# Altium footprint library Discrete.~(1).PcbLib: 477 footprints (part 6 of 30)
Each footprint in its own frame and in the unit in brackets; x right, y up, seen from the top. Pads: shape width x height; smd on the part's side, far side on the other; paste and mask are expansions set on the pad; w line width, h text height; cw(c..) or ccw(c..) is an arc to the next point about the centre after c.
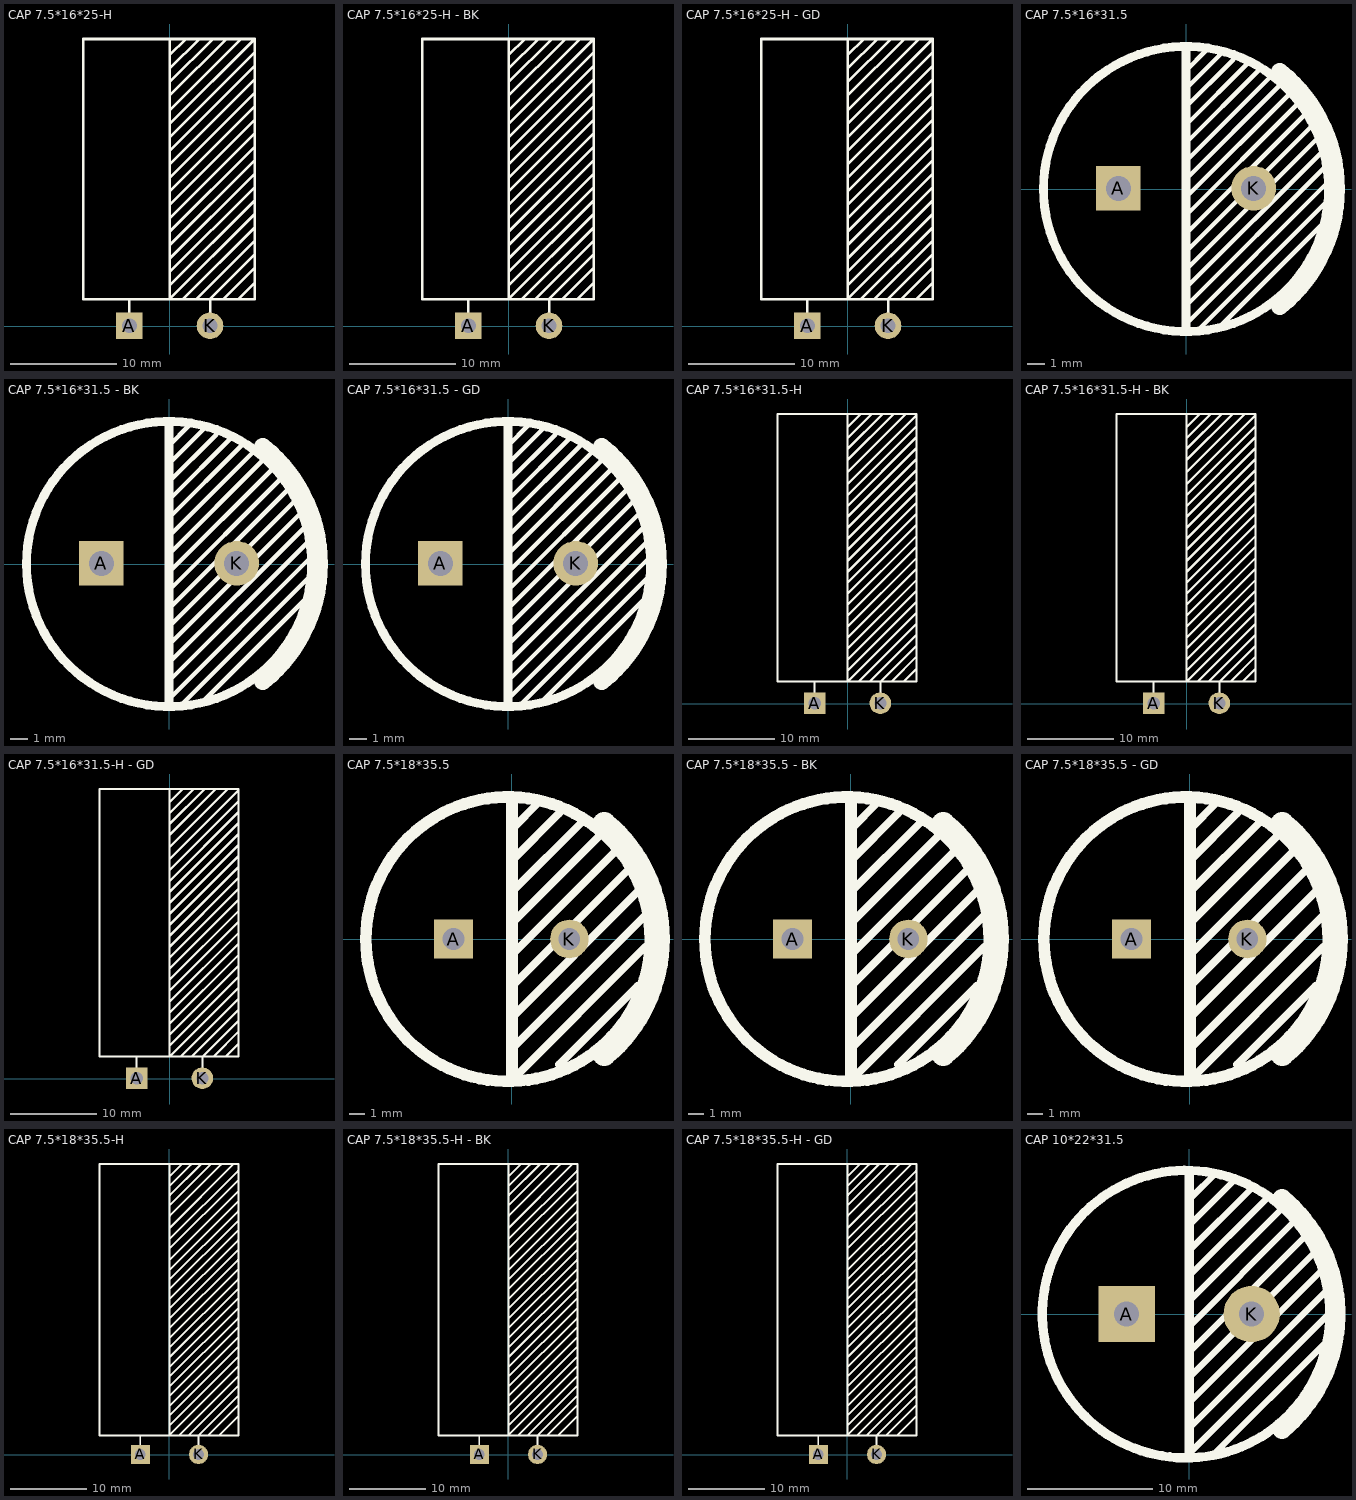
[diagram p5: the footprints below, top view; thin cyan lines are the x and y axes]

## CAP 7.5*16*25-H [mm] "脚距7.5mm直径16mm高度25mm"
pads (2):
  rect 2.5x2.5 hole 1.4: A(-3.8,0.038)
  round 2.5 hole 1.4: K(3.8,0.038)
Top Overlay:
  lines w0.254: -3.81,1.27 -3.81,2.54 ; 0,3.81 8.001,11.811 ; 0,5.08 8.001,13.081 ; 0,6.35 8.001,14.351 ; 0,7.62 7.938,15.557 ; 0,8.89 8.001,16.891 ; 0,10.16 7.938,18.098 ; 0,11.43 8.001,19.431 ; 0,12.7 7.938,20.637 ; 0,13.97 7.938,21.907 ; 0,15.24 7.938,23.177 ; 0,16.51 7.938,24.447 ; 0,17.78 7.938,25.717 ; 0,19.05 7.929,26.979 ; 0,20.32 6.731,27.051 ; 0,21.717 5.334,27.051 ; 0,22.987 4.064,27.051 ; 0,24.257 2.794,27.051 ; 0,25.527 1.524,27.051 ; 0,27.051 0,2.54 8.001,10.541 ; 1.27,2.54 8.001,9.271 ; 2.54,2.54 8.001,8.001 ; 3.81,1.27 3.81,2.54 8.001,6.731 ; 5.08,2.54 8.001,5.461 ; 6.477,2.54 8.001,4.064 ; -8.128,2.54 8.001,2.54 8.001,27.051 -8.128,27.051 -8.128,2.54
3D body "CAP 7.5X16X25-H.STEP": height 16.03, standoff -3.47, extent -8.05,-0.462 7.96,26.948

## CAP 7.5*16*25-H - BK [mm] "脚距7.5mm直径16mm高度25mm"
pads (2):
  rect 2.5x2.5 hole 1.4: A(-3.8,0.038)
  round 2.5 hole 1.4: K(3.8,0.038)
Top Overlay:
  lines w0.254: -3.81,1.27 -3.81,2.54 ; 0,3.81 8.001,11.811 ; 0,5.08 8.001,13.081 ; 0,6.35 8.001,14.351 ; 0,7.62 7.938,15.557 ; 0,8.89 8.001,16.891 ; 0,10.16 7.938,18.098 ; 0,11.43 8.001,19.431 ; 0,12.7 7.938,20.637 ; 0,13.97 7.938,21.907 ; 0,15.24 7.938,23.177 ; 0,16.51 7.938,24.447 ; 0,17.78 7.938,25.717 ; 0,19.05 7.929,26.979 ; 0,20.32 6.731,27.051 ; 0,21.717 5.334,27.051 ; 0,22.987 4.064,27.051 ; 0,24.257 2.794,27.051 ; 0,25.527 1.524,27.051 ; 0,27.051 0,2.54 8.001,10.541 ; 1.27,2.54 8.001,9.271 ; 2.54,2.54 8.001,8.001 ; 3.81,1.27 3.81,2.54 8.001,6.731 ; 5.08,2.54 8.001,5.461 ; 6.477,2.54 8.001,4.064 ; -8.128,2.54 -8.128,27.051 8.001,27.051 8.001,2.54 -8.128,2.54
3D body "CAP 7.5X16X25-H.STEP": height 16.03, standoff -3.48, extent -8.05,-0.462 7.96,26.948

## CAP 7.5*16*25-H - GD [mm] "脚距7.5mm直径16mm高度25mm"
pads (2):
  rect 2.5x2.5 hole 1.4: A(-3.8,0.038)
  round 2.5 hole 1.4: K(3.8,0.038)
Top Overlay:
  lines w0.254: -3.81,1.27 -3.81,2.54 ; 0,3.81 8.001,11.811 ; 0,5.08 8.001,13.081 ; 0,6.35 8.001,14.351 ; 0,7.62 7.938,15.557 ; 0,8.89 8.001,16.891 ; 0,10.16 7.938,18.098 ; 0,11.43 8.001,19.431 ; 0,12.7 7.938,20.637 ; 0,13.97 7.938,21.907 ; 0,15.24 7.938,23.177 ; 0,16.51 7.938,24.447 ; 0,17.78 7.938,25.717 ; 0,19.05 7.929,26.979 ; 0,20.32 6.731,27.051 ; 0,21.717 5.334,27.051 ; 0,22.987 4.064,27.051 ; 0,24.257 2.794,27.051 ; 0,25.527 1.524,27.051 ; 0,27.051 0,2.54 8.001,10.541 ; 1.27,2.54 8.001,9.271 ; 2.54,2.54 8.001,8.001 ; 3.81,1.27 3.81,2.54 8.001,6.731 ; 5.08,2.54 8.001,5.461 ; 6.477,2.54 8.001,4.064 ; -8.128,2.54 -8.128,27.051 8.001,27.051 8.001,2.54 -8.128,2.54
3D body "CAP 7.5X16X25-H.STEP": height 16.03, standoff -3.48, extent -8.05,-0.462 7.96,26.948

## CAP 7.5*16*31.5 [mm] "脚距7.5mm直径16mm高度31.5mm"
pads (2):
  rect 2.5x2.5 hole 1.4: A(-3.8,0.038)
  round 2.5 hole 1.4: K(3.8,0.038)
Top Overlay:
  circle w0.5: c0,0 r8
  lines w0.254: 0,-7.582 8.001,0.419 ; 0,-6.566 7.874,1.308 ; 0,-5.55 7.62,2.07 ; 0,-4.534 7.366,2.832 ; 0,-3.518 6.972,3.454 ; 0,-2.502 6.604,4.102 ; 0,-1.486 6.223,4.737 ; 0,-0.47 5.905,5.436 ; 0,0.546 5.296,5.842 ; 0,1.562 4.826,6.388 ; 0,2.578 4.064,6.642 ; 0,3.594 3.556,7.15 ; 0,4.61 2.54,7.15 2.769,7.379 ; 0,5.626 2.032,7.658 ; 0,6.642 1.143,7.785 ; 0.66,-7.938 7.938,-0.66 ; 2.032,-7.582 6.604,-3.01 7.81,-1.803
  lines w0.5: 0,-7.963 0,7.963
  lines w1: 5.259,-6.574 ccw(c0,0) 5.259,6.574
3D body "CAP 7.5X16X31.STEP": height 31.53, standoff -3.38, extent -8,-7.998 8.01,7.998

## CAP 7.5*16*31.5 - BK [mm] "脚距7.5mm直径16mm高度31.5mm"
pads (2):
  rect 2.5x2.5 hole 1.4: A(-3.8,0.038)
  round 2.5 hole 1.4: K(3.8,0.038)
Top Overlay:
  circle w0.5: c0,0 r8
  lines w0.254: 0,-7.582 8.001,0.419 ; 0,-6.566 7.874,1.308 ; 0,-5.55 7.62,2.07 ; 0,-4.534 7.366,2.832 ; 0,-3.518 6.972,3.454 ; 0,-2.502 6.604,4.102 ; 0,-1.486 6.223,4.737 ; 0,-0.47 5.905,5.436 ; 0,0.546 5.296,5.842 ; 0,1.562 4.826,6.388 ; 0,2.578 4.064,6.642 ; 0,3.594 3.556,7.15 ; 0,4.61 2.54,7.15 2.769,7.379 ; 0,5.626 2.032,7.658 ; 0,6.642 1.143,7.785 ; 0.66,-7.938 7.938,-0.66 ; 2.032,-7.582 6.604,-3.01 7.81,-1.803
  lines w0.5: 0,-7.963 0,7.963
  lines w1: 5.259,-6.574 ccw(c0,0) 5.259,6.574
3D body "CAP 7.5X16X31.5.STEP": height 31.54, standoff -3.37, extent -8,-7.998 8.01,7.998

## CAP 7.5*16*31.5 - GD [mm] "脚距7.5mm直径16mm高度31.5mm"
pads (2):
  rect 2.5x2.5 hole 1.4: A(-3.8,0.038)
  round 2.5 hole 1.4: K(3.8,0.038)
Top Overlay:
  circle w0.5: c0,0 r8
  lines w0.254: 0,-7.582 8.001,0.419 ; 0,-6.566 7.874,1.308 ; 0,-5.55 7.62,2.07 ; 0,-4.534 7.366,2.832 ; 0,-3.518 6.972,3.454 ; 0,-2.502 6.604,4.102 ; 0,-1.486 6.223,4.737 ; 0,-0.47 5.905,5.436 ; 0,0.546 5.296,5.842 ; 0,1.562 4.826,6.388 ; 0,2.578 4.064,6.642 ; 0,3.594 3.556,7.15 ; 0,4.61 2.54,7.15 2.769,7.379 ; 0,5.626 2.032,7.658 ; 0,6.642 1.143,7.785 ; 0.66,-7.938 7.938,-0.66 ; 2.032,-7.582 6.604,-3.01 7.81,-1.803
  lines w0.5: 0,-7.963 0,7.963
  lines w1: 5.259,-6.574 ccw(c0,0) 5.259,6.574
3D body "CAP 7.5X16X31.5.STEP": height 31.54, standoff -3.37, extent -8,-7.998 8.01,7.998

## CAP 7.5*16*31.5-H [mm] "脚距7.5mm直径16mm高度31.5mm"
pads (2):
  rect 2.5x2.5 hole 1.4: A(-3.8,0.038)
  round 2.5 hole 1.4: K(3.8,0.038)
Top Overlay:
  lines w0.254: -3.81,1.27 -3.81,2.54 ; 0,3.81 8.001,11.811 ; 0,5.08 8.001,13.081 ; 0,6.35 8.001,14.351 ; 0,7.62 7.938,15.557 ; 0,8.89 8.001,16.891 ; 0,10.16 7.938,18.098 ; 0,11.43 8.001,19.431 ; 0,12.7 7.938,20.637 ; 0,13.97 7.938,21.907 ; 0,15.24 7.938,23.177 ; 0,16.51 7.938,24.447 ; 0,17.78 7.938,25.717 ; 0,19.05 7.929,26.979 ; 0,20.32 7.938,28.258 ; 0,21.59 7.938,29.527 ; 0,22.86 7.938,30.797 ; 0,24.13 7.938,32.067 ; 0,25.4 7.929,33.329 ; 0,26.797 6.731,33.528 ; 0,28.194 5.334,33.528 ; 0,29.464 4.064,33.528 ; 0,30.734 2.794,33.528 ; 0,32.004 1.524,33.528 ; 0,33.528 0,2.54 8.001,10.541 ; 1.27,2.54 8.001,9.271 ; 2.54,2.54 8.001,8.001 ; 3.81,1.27 3.81,2.54 8.001,6.731 ; 5.08,2.54 8.001,5.461 ; 6.477,2.54 8.001,4.064 ; -8.128,2.54 -8.128,33.528 8.001,33.528 8.001,2.54 -8.128,2.54
3D body "CAP 7.5X16X31.5-H.STEP": height 16.03, standoff -3.47, extent -8.05,-0.462 7.96,33.448

## CAP 7.5*16*31.5-H - BK [mm] "脚距7.5mm直径16mm高度31.5mm"
pads (2):
  rect 2.5x2.5 hole 1.4: A(-3.8,0.038)
  round 2.5 hole 1.4: K(3.8,0.038)
Top Overlay:
  lines w0.254: -3.81,1.27 -3.81,2.54 ; 0,3.81 8.001,11.811 ; 0,5.08 8.001,13.081 ; 0,6.35 8.001,14.351 ; 0,7.62 7.938,15.557 ; 0,8.89 8.001,16.891 ; 0,10.16 7.938,18.098 ; 0,11.43 8.001,19.431 ; 0,12.7 7.938,20.637 ; 0,13.97 7.938,21.907 ; 0,15.24 7.938,23.177 ; 0,16.51 7.938,24.447 ; 0,17.78 7.938,25.717 ; 0,19.05 7.929,26.979 ; 0,20.32 7.938,28.258 ; 0,21.59 7.938,29.527 ; 0,22.86 7.938,30.797 ; 0,24.13 7.938,32.067 ; 0,25.4 7.929,33.329 ; 0,26.797 6.731,33.528 ; 0,28.194 5.334,33.528 ; 0,29.464 4.064,33.528 ; 0,30.734 2.794,33.528 ; 0,32.004 1.524,33.528 ; 0,33.528 0,2.54 8.001,10.541 ; 1.27,2.54 8.001,9.271 ; 2.54,2.54 8.001,8.001 ; 3.81,1.27 3.81,2.54 8.001,6.731 ; 5.08,2.54 8.001,5.461 ; 6.477,2.54 8.001,4.064 ; -8.128,2.54 -8.128,33.528 8.001,33.528 8.001,2.54 -8.128,2.54
3D body "CAP 7.5X16X31.5-H.STEP": height 16.03, standoff -3.48, extent -8.05,-0.462 7.96,33.448

## CAP 7.5*16*31.5-H - GD [mm] "脚距7.5mm直径16mm高度31.5mm"
pads (2):
  rect 2.5x2.5 hole 1.4: A(-3.8,0.038)
  round 2.5 hole 1.4: K(3.8,0.038)
Top Overlay:
  lines w0.254: -3.81,1.27 -3.81,2.54 ; 0,3.81 8.001,11.811 ; 0,5.08 8.001,13.081 ; 0,6.35 8.001,14.351 ; 0,7.62 7.938,15.557 ; 0,8.89 8.001,16.891 ; 0,10.16 7.938,18.098 ; 0,11.43 8.001,19.431 ; 0,12.7 7.938,20.637 ; 0,13.97 7.938,21.907 ; 0,15.24 7.938,23.177 ; 0,16.51 7.938,24.447 ; 0,17.78 7.938,25.717 ; 0,19.05 7.929,26.979 ; 0,20.32 7.938,28.258 ; 0,21.59 7.938,29.527 ; 0,22.86 7.938,30.797 ; 0,24.13 7.938,32.067 ; 0,25.4 7.929,33.329 ; 0,26.797 6.731,33.528 ; 0,28.194 5.334,33.528 ; 0,29.464 4.064,33.528 ; 0,30.734 2.794,33.528 ; 0,32.004 1.524,33.528 ; 0,33.528 0,2.54 8.001,10.541 ; 1.27,2.54 8.001,9.271 ; 2.54,2.54 8.001,8.001 ; 3.81,1.27 3.81,2.54 8.001,6.731 ; 5.08,2.54 8.001,5.461 ; 6.477,2.54 8.001,4.064 ; -8.128,2.54 -8.128,33.528 8.001,33.528 8.001,2.54 -8.128,2.54
3D body "CAP 7.5X16X31.5-H.STEP": height 16.03, standoff -3.48, extent -8.05,-0.462 7.96,33.448

## CAP 7.5*18*35.5 [mm] "脚距7.5mm直径18mm高度35.5mm"
pads (2):
  rect 2.5x2.5 hole 1.4: A(-3.78,0)
  round 2.5 hole 1.4: K(3.72,0)
Top Overlay:
  circle w0.754: c-0.248,-0.013 r9.2
  lines w0.504: 0,-9.144 8.636,-0.508 ; 0,-7.112 8.636,1.524 ; 0,-5.08 8.128,3.048 ; 0,-3.048 7.62,4.572 ; 0,-1.016 6.731,5.715 ; 0,1.016 5.715,6.731 ; 0,3.048 4.572,7.62 ; 0,5.08 3.048,8.128 ; 0,7.112 1.778,8.89 ; 3.048,-8.128 8.128,-3.048
  lines w0.754: 0,-8.8 0,8.8
  lines w1.524: 5.959,-7.456 ccw(c-0.254,0) 5.959,7.456
3D body "CAP 7.5X18X35.5.STEP": height 35.54, standoff -3.37, extent -9,-8.997 9.01,8.997

## CAP 7.5*18*35.5 - BK [mm] "脚距7.5mm直径18mm高度35.5mm"
pads (2):
  rect 2.5x2.5 hole 1.4: A(-3.78,0)
  round 2.5 hole 1.4: K(3.72,0)
Top Overlay:
  circle w0.754: c-0.248,-0.013 r9.2
  lines w0.504: 0,-9.144 8.636,-0.508 ; 0,-7.112 8.636,1.524 ; 0,-5.08 8.128,3.048 ; 0,-3.048 7.62,4.572 ; 0,-1.016 6.731,5.715 ; 0,1.016 5.715,6.731 ; 0,3.048 4.572,7.62 ; 0,5.08 3.048,8.128 ; 0,7.112 1.778,8.89 ; 3.048,-8.128 8.128,-3.048
  lines w0.754: 0,-8.8 0,8.8
  lines w1.524: 5.959,-7.456 ccw(c-0.254,0) 5.959,7.456
3D body "CAP 7.5X18X35.5.STEP": height 35.54, standoff -3.37, extent -9,-8.997 9.01,8.997

## CAP 7.5*18*35.5 - GD [mm] "脚距7.5mm直径18mm高度35.5mm"
pads (2):
  rect 2.5x2.5 hole 1.4: A(-3.78,0)
  round 2.5 hole 1.4: K(3.72,0)
Top Overlay:
  circle w0.754: c-0.248,-0.013 r9.2
  lines w0.504: 0,-9.144 8.636,-0.508 ; 0,-7.112 8.636,1.524 ; 0,-5.08 8.128,3.048 ; 0,-3.048 7.62,4.572 ; 0,-1.016 6.731,5.715 ; 0,1.016 5.715,6.731 ; 0,3.048 4.572,7.62 ; 0,5.08 3.048,8.128 ; 0,7.112 1.778,8.89 ; 3.048,-8.128 8.128,-3.048
  lines w0.754: 0,-8.8 0,8.8
  lines w1.524: 5.959,-7.456 ccw(c-0.254,0) 5.959,7.456
3D body "CAP 7.5X18X35.5.STEP": height 35.56, standoff -3.35, extent -8.989,-8.992 9.021,9.002

## CAP 7.5*18*35.5-H [mm] "脚距7.5mm直径18mm高度35.5mm"
pads (2):
  rect 2.5x2.5 hole 1.4: A(-3.8,0.038)
  round 2.5 hole 1.4: K(3.8,0.038)
Top Overlay:
  lines w0.254: -3.81,1.27 -3.81,2.54 ; 0,3.81 8.955,12.765 ; 0,5.08 8.95,14.03 ; 0,6.35 8.975,15.325 ; 0,7.62 8.94,16.56 ; 0,8.89 8.965,17.855 ; 0,10.16 8.99,19.15 ; 0,11.43 8.985,20.415 ; 0,12.7 8.98,21.68 ; 0,13.97 8.975,22.945 ; 0,15.24 8.97,24.21 ; 0,16.51 8.965,25.475 ; 0,17.78 8.99,26.77 ; 0,19.05 8.985,28.035 ; 0,20.32 8.98,29.3 ; 0,21.59 8.975,30.565 ; 0,22.86 8.97,31.83 ; 0,24.13 8.965,33.095 ; 0,25.4 8.99,34.39 ; 0,26.88 8.97,35.85 ; 0,28.15 8.965,37.115 ; 0,37.98 0,2.54 8.99,11.53 ; 0.02,29.62 8.36,37.96 ; 0.06,31.2 6.791,37.931 ; 0.06,32.597 5.394,37.931 ; 0.06,33.867 4.124,37.931 ; 0.06,35.137 2.854,37.931 ; 0.06,36.407 1.584,37.931 ; 1.27,2.54 8.995,10.265 ; 2.54,2.54 8.94,8.94 ; 3.81,1.27 3.81,2.54 9.005,7.735 ; 5.08,2.54 8.98,6.44 ; 6.477,2.54 8.989,5.052 ; -9.12,2.54 9,2.54 9,37.98 -9.12,37.98 -9.12,2.54
3D body "CAP 7.5X18X35.5-H.STEP": height 18.03, standoff -3.47, extent -9.05,-0.462 8.96,37.948

## CAP 7.5*18*35.5-H - BK [mm] "脚距7.5mm直径18mm高度35.5mm"
pads (2):
  rect 2.5x2.5 hole 1.4: A(-3.8,0.038)
  round 2.5 hole 1.4: K(3.8,0.038)
Top Overlay:
  lines w0.254: -3.81,1.27 -3.81,2.54 ; 0,3.81 8.955,12.765 ; 0,5.08 8.95,14.03 ; 0,6.35 8.975,15.325 ; 0,7.62 8.94,16.56 ; 0,8.89 8.965,17.855 ; 0,10.16 8.99,19.15 ; 0,11.43 8.985,20.415 ; 0,12.7 8.98,21.68 ; 0,13.97 8.975,22.945 ; 0,15.24 8.97,24.21 ; 0,16.51 8.965,25.475 ; 0,17.78 8.99,26.77 ; 0,19.05 8.985,28.035 ; 0,20.32 8.98,29.3 ; 0,21.59 8.975,30.565 ; 0,22.86 8.97,31.83 ; 0,24.13 8.965,33.095 ; 0,25.4 8.99,34.39 ; 0,26.88 8.97,35.85 ; 0,28.15 8.965,37.115 ; 0,37.98 0,2.54 8.99,11.53 ; 0.02,29.62 8.36,37.96 ; 0.06,31.2 6.791,37.931 ; 0.06,32.597 5.394,37.931 ; 0.06,33.867 4.124,37.931 ; 0.06,35.137 2.854,37.931 ; 0.06,36.407 1.584,37.931 ; 1.27,2.54 8.995,10.265 ; 2.54,2.54 8.94,8.94 ; 3.81,1.27 3.81,2.54 9.005,7.735 ; 5.08,2.54 8.98,6.44 ; 6.477,2.54 8.989,5.052 ; -9.12,2.54 9,2.54 9,37.98 -9.12,37.98 -9.12,2.54
3D body "CAP 7.5X18X35.5-H.STEP": height 18.03, standoff -3.48, extent -9.05,-0.462 8.96,37.948

## CAP 7.5*18*35.5-H - GD [mm] "脚距7.5mm直径18mm高度35.5mm"
pads (2):
  rect 2.5x2.5 hole 1.4: A(-3.8,0.038)
  round 2.5 hole 1.4: K(3.8,0.038)
Top Overlay:
  lines w0.254: -3.81,1.27 -3.81,2.54 ; 0,3.81 8.955,12.765 ; 0,5.08 8.95,14.03 ; 0,6.35 8.975,15.325 ; 0,7.62 8.94,16.56 ; 0,8.89 8.965,17.855 ; 0,10.16 8.99,19.15 ; 0,11.43 8.985,20.415 ; 0,12.7 8.98,21.68 ; 0,13.97 8.975,22.945 ; 0,15.24 8.97,24.21 ; 0,16.51 8.965,25.475 ; 0,17.78 8.99,26.77 ; 0,19.05 8.985,28.035 ; 0,20.32 8.98,29.3 ; 0,21.59 8.975,30.565 ; 0,22.86 8.97,31.83 ; 0,24.13 8.965,33.095 ; 0,25.4 8.99,34.39 ; 0,26.88 8.97,35.85 ; 0,28.15 8.965,37.115 ; 0,37.98 0,2.54 8.99,11.53 ; 0.02,29.62 8.36,37.96 ; 0.06,31.2 6.791,37.931 ; 0.06,32.597 5.394,37.931 ; 0.06,33.867 4.124,37.931 ; 0.06,35.137 2.854,37.931 ; 0.06,36.407 1.584,37.931 ; 1.27,2.54 8.995,10.265 ; 2.54,2.54 8.94,8.94 ; 3.81,1.27 3.81,2.54 9.005,7.735 ; 5.08,2.54 8.98,6.44 ; 6.477,2.54 8.989,5.052 ; -9.12,2.54 -9.12,37.98 9,37.98 9,2.54 -9.12,2.54
3D body "CAP 7.5X18X35.5-H.STEP": height 18.03, standoff -3.48, extent -9.05,-0.462 8.96,37.948

## CAP 10*22*31.5 [mm] "脚距10mm直径22mm高度31.5mm"
pads (2):
  rect 4.5x4.5 hole 2: A(-5,0)
  round 4.5 hole 2: K(5,0)
Top Overlay:
  circle w0.754: c-0.248,-0.013 r11.5
  lines w0.504: 0,-7.112 10.541,3.429 ; 0,-5.08 10.033,4.953 ; 0,-3.048 9.271,6.223 ; 0,-1.016 8.382,7.366 ; 0,1.016 7.493,8.509 ; 0,3.048 6.223,9.271 ; 0,5.08 4.953,10.033 ; 0,7.112 3.556,10.668 ; 0.254,-10.922 11.43,0.254 ; 0.254,-8.89 11.43,2.286 ; 0.254,9.398 2.032,11.176 ; 1.778,-11.43 11.049,-2.159
  lines w0.754: 0,-11.25 0,11.25
  lines w1.524: 7.428,-9.219 ccw(c-0.254,0) 7.428,9.219
3D body "CAP 10X22X31.5.STEP": height 31.53, standoff -3.38, extent -11,-10.997 11.01,10.997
